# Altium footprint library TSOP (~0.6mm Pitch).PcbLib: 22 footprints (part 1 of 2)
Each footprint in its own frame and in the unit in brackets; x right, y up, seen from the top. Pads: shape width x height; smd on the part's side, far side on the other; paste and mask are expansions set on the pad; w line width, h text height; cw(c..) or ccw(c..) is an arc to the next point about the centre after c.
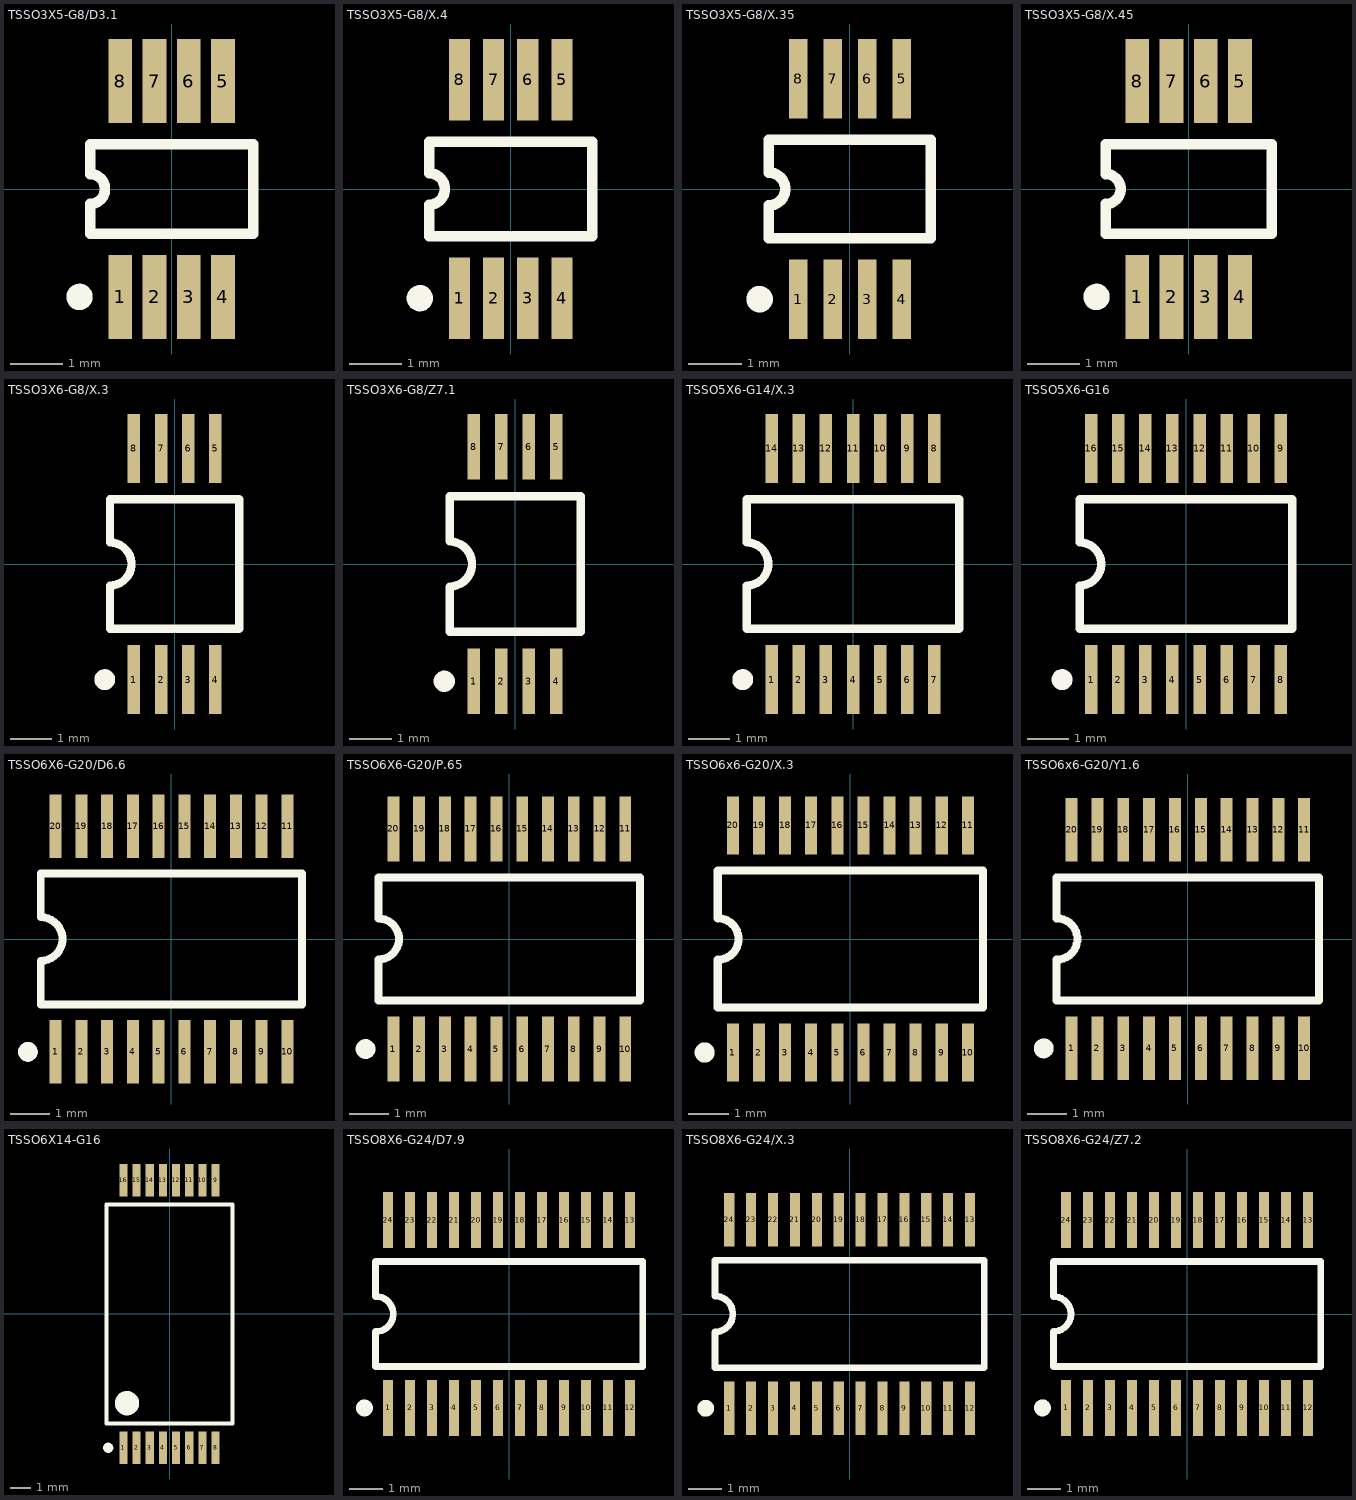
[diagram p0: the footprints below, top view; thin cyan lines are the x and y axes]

## TSSO3X5-G8/D3.1 [mm]
pads (8):
  rect 0.45x1.6 smd: 1(-0.975,-2.05) 2(-0.325,-2.05) 3(0.325,-2.05) 4(0.975,-2.05) 5(0.975,2.05) 6(0.325,2.05) 7(-0.325,2.05) 8(-0.975,2.05)
Top Overlay:
  circle w0.25: c-1.75,-2.05 r0.125
  lines w0.2: -1.55,-0.85 1.55,-0.85 1.55,0.85 -1.55,0.85 -1.55,0.283 cw(c-1.55,0) -1.55,-0.283 -1.55,-0.85

## TSSO3X5-G8/X.4 [mm]
pads (8):
  rect 0.4x1.55 smd: 1(-0.975,-2.075) 2(-0.325,-2.075) 3(0.325,-2.075) 4(0.975,-2.075) 5(0.975,2.075) 6(0.325,2.075) 7(-0.325,2.075) 8(-0.975,2.075)
Top Overlay:
  circle w0.25: c-1.725,-2.075 r0.125
  lines w0.2: -1.55,-0.9 1.55,-0.9 1.55,0.9 -1.55,0.9 -1.55,0.3 cw(c-1.55,0) -1.55,-0.3 -1.55,-0.9

## TSSO3X5-G8/X.35 [mm]
pads (8):
  rect 0.35x1.5 smd: 1(-0.975,-2.075) 2(-0.325,-2.075) 3(0.325,-2.075) 4(0.975,-2.075) 5(0.975,2.075) 6(0.325,2.075) 7(-0.325,2.075) 8(-0.975,2.075)
Top Overlay:
  circle w0.25: c-1.7,-2.075 r0.125
  lines w0.2: -1.525,-0.925 -1.525,-0.308 ccw(c-1.525,0) -1.525,0.308 -1.525,0.925 1.525,0.925 1.525,-0.925 -1.525,-0.925

## TSSO3X5-G8/X.45 [mm]
pads (8):
  rect 0.45x1.6 smd: 1(-0.975,-2.05) 2(-0.325,-2.05) 3(0.325,-2.05) 4(0.975,-2.05) 5(0.975,2.05) 6(0.325,2.05) 7(-0.325,2.05) 8(-0.975,2.05)
Top Overlay:
  circle w0.25: c-1.75,-2.05 r0.125
  lines w0.2: -1.575,-0.85 -1.575,-0.283 ccw(c-1.575,0) -1.575,0.283 -1.575,0.85 1.575,0.85 1.575,-0.85 -1.575,-0.85

## TSSO3X6-G8/X.3 [mm]
pads (8):
  rect 0.3x1.65 smd: 1(-0.975,-2.775) 2(-0.325,-2.775) 3(0.325,-2.775) 4(0.975,-2.775) 5(0.975,2.775) 6(0.325,2.775) 7(-0.325,2.775) 8(-0.975,2.775)
Top Overlay:
  circle w0.25: c-1.675,-2.775 r0.125
  lines w0.2: -1.55,-1.55 1.55,-1.55 1.55,1.55 -1.55,1.55 -1.55,0.517 cw(c-1.55,0) -1.55,-0.517 -1.55,-1.55

## TSSO3X6-G8/Z7.1 [mm]
pads (8):
  rect 0.3x1.55 smd: 1(-0.975,-2.775) 2(-0.325,-2.775) 3(0.325,-2.775) 4(0.975,-2.775) 5(0.975,2.775) 6(0.325,2.775) 7(-0.325,2.775) 8(-0.975,2.775)
Top Overlay:
  circle w0.25: c-1.675,-2.775 r0.125
  lines w0.2: -1.55,-1.6 1.55,-1.6 1.55,1.6 -1.55,1.6 -1.55,0.533 cw(c-1.55,0) -1.55,-0.533 -1.55,-1.6

## TSSO5X6-G14/X.3 [mm]
pads (14):
  rect 0.3x1.65 smd: 1(-1.95,-2.775) 2(-1.3,-2.775) 3(-0.65,-2.775) 4(0,-2.775) 5(0.65,-2.775) 6(1.3,-2.775) 7(1.95,-2.775) 8(1.95,2.775) 9(1.3,2.775) 10(0.65,2.775) 11(0,2.775) 12(-0.65,2.775) 13(-1.3,2.775) 14(-1.95,2.775)
Top Overlay:
  circle w0.25: c-2.65,-2.775 r0.125
  lines w0.2: -2.55,-1.55 2.55,-1.55 2.55,1.55 -2.55,1.55 -2.55,0.517 cw(c-2.55,0) -2.55,-0.517 -2.55,-1.55

## TSSO5X6-G16 [mm]
pads (16):
  rect 0.3x1.65 smd: 1(-2.275,-2.775) 2(-1.625,-2.775) 3(-0.975,-2.775) 4(-0.325,-2.775) 5(0.325,-2.775) 6(0.975,-2.775) 7(1.625,-2.775) 8(2.275,-2.775) 9(2.275,2.775) 10(1.625,2.775) 11(0.975,2.775) 12(0.325,2.775) 13(-0.325,2.775) 14(-0.975,2.775) 15(-1.625,2.775) 16(-2.275,2.775)
Top Overlay:
  circle w0.25: c-2.975,-2.775 r0.125
  lines w0.2: -2.55,-1.55 -2.55,-0.517 ccw(c-2.55,0) -2.55,0.517 -2.55,1.55 2.55,1.55 2.55,-1.55 -2.55,-1.55

## TSSO6X6-G20/D6.6 [mm]
pads (20):
  rect 0.3x1.6 smd: 1(-2.925,-2.85) 2(-2.275,-2.85) 3(-1.625,-2.85) 4(-0.975,-2.85) 5(-0.325,-2.85) 6(0.325,-2.85) 7(0.975,-2.85) 8(1.625,-2.85) 9(2.275,-2.85) 10(2.925,-2.85) 11(2.925,2.85) 12(2.275,2.85) 13(1.625,2.85) 14(0.975,2.85) 15(0.325,2.85) 16(-0.325,2.85) 17(-0.975,2.85) 18(-1.625,2.85) 19(-2.275,2.85) 20(-2.925,2.85)
Top Overlay:
  circle w0.25: c-3.625,-2.85 r0.125
  lines w0.2: -3.3,-1.65 -3.3,-0.55 ccw(c-3.3,0) -3.3,0.55 -3.3,1.65 3.3,1.65 3.3,-1.65 -3.3,-1.65

## TSSO6X6-G20/P.65 [mm]
pads (20):
  rect 0.3x1.65 smd: 1(-2.925,-2.775) 2(-2.275,-2.775) 3(-1.625,-2.775) 4(-0.975,-2.775) 5(-0.325,-2.775) 6(0.325,-2.775) 7(0.975,-2.775) 8(1.625,-2.775) 9(2.275,-2.775) 10(2.925,-2.775) 11(2.925,2.775) 12(2.275,2.775) 13(1.625,2.775) 14(0.975,2.775) 15(0.325,2.775) 16(-0.325,2.775) 17(-0.975,2.775) 18(-1.625,2.775) 19(-2.275,2.775) 20(-2.925,2.775)
Top Overlay:
  circle w0.25: c-3.625,-2.775 r0.125
  lines w0.2: -3.3,-1.55 -3.3,-0.517 ccw(c-3.3,0) -3.3,0.517 -3.3,1.55 3.3,1.55 3.3,-1.55 -3.3,-1.55

## TSSO6x6-G20/X.3 [mm]
pads (20):
  rect 0.3x1.45 smd: 1(-2.925,-2.825) 2(-2.275,-2.825) 3(-1.625,-2.825) 4(-0.975,-2.825) 5(-0.325,-2.825) 6(0.325,-2.825) 7(0.975,-2.825) 8(1.625,-2.825) 9(2.275,-2.825) 10(2.925,-2.825) 11(2.925,2.825) 12(2.275,2.825) 13(1.625,2.825) 14(0.975,2.825) 15(0.325,2.825) 16(-0.325,2.825) 17(-0.975,2.825) 18(-1.625,2.825) 19(-2.275,2.825) 20(-2.925,2.825)
Top Overlay:
  circle w0.25: c-3.625,-2.825 r0.125
  lines w0.2: -3.3,-0.52 -3.3,-1.7 3.3,-1.7 3.3,1.7 -3.3,1.7 -3.3,0.52 ; -3.3,-0.517 ccw(c-3.3,0) -3.3,0.517

## TSSO6x6-G20/Y1.6 [mm]
pads (20):
  rect 0.3x1.6 smd: 1(-2.925,-2.75) 2(-2.275,-2.75) 3(-1.625,-2.75) 4(-0.975,-2.75) 5(-0.325,-2.75) 6(0.325,-2.75) 7(0.975,-2.75) 8(1.625,-2.75) 9(2.275,-2.75) 10(2.925,-2.75) 11(2.925,2.75) 12(2.275,2.75) 13(1.625,2.75) 14(0.975,2.75) 15(0.325,2.75) 16(-0.325,2.75) 17(-0.975,2.75) 18(-1.625,2.75) 19(-2.275,2.75) 20(-2.925,2.75)
Top Overlay:
  circle w0.25: c-3.625,-2.75 r0.125
  lines w0.2: -3.3,-1.55 3.3,-1.55 3.3,1.55 -3.3,1.55 -3.3,0.52 cw(c-3.3,0) -3.3,-0.52 -3.3,-1.55

## TSSO6X14-G16 [mm]
pads (16):
  rect 0.4x1.6 smd: 1(-2.275,-6.6) 2(-1.625,-6.6) 3(-0.975,-6.6) 4(-0.325,-6.6) 5(0.325,-6.6) 6(0.975,-6.6) 7(1.625,-6.6) 8(2.275,-6.6) 9(2.275,6.6) 10(1.625,6.6) 11(0.975,6.6) 12(0.325,6.6) 13(-0.325,6.6) 14(-0.975,6.6) 15(-1.625,6.6) 16(-2.275,6.6)
Top Overlay:
  circle w0.6: c-2.1,-4.4 r0.3
  circle w0.25: c-3.025,-6.6 r0.125
  lines w0.2: -3.1,-5.4 3.1,-5.4 3.1,5.4 -3.1,5.4 -3.1,-0.635 -3.1,-5.4

## TSSO8X6-G24/D7.9 [mm]
pads (24):
  rect 0.3x1.65 smd: 1(-3.575,-2.775) 2(-2.925,-2.775) 3(-2.275,-2.775) 4(-1.625,-2.775) 5(-0.975,-2.775) 6(-0.325,-2.775) 7(0.325,-2.775) 8(0.975,-2.775) 9(1.625,-2.775) 10(2.275,-2.775) 11(2.925,-2.775) 12(3.575,-2.775) 13(3.575,2.775) 14(2.925,2.775) 15(2.275,2.775) 16(1.625,2.775) 17(0.975,2.775) 18(0.325,2.775) 19(-0.325,2.775) 20(-0.975,2.775) 21(-1.625,2.775) 22(-2.275,2.775) 23(-2.925,2.775) 24(-3.575,2.775)
Top Overlay:
  circle w0.25: c-4.275,-2.775 r0.125
  lines w0.2: -3.95,-0.52 -3.95,-1.55 3.95,-1.55 3.95,1.55 -3.95,1.55 -3.95,0.52 ; -3.943,-0.52 ccw(c-3.943,0) -3.943,0.52

## TSSO8X6-G24/X.3 [mm]
pads (24):
  rect 0.3x1.6 smd: 1(-3.575,-2.8) 2(-2.925,-2.8) 3(-2.275,-2.8) 4(-1.625,-2.8) 5(-0.975,-2.8) 6(-0.325,-2.8) 7(0.325,-2.8) 8(0.975,-2.8) 9(1.625,-2.8) 10(2.275,-2.8) 11(2.925,-2.8) 12(3.575,-2.8) 13(3.575,2.8) 14(2.925,2.8) 15(2.275,2.8) 16(1.625,2.8) 17(0.975,2.8) 18(0.325,2.8) 19(-0.325,2.8) 20(-0.975,2.8) 21(-1.625,2.8) 22(-2.275,2.8) 23(-2.925,2.8) 24(-3.575,2.8)
Top Overlay:
  circle w0.25: c-4.275,-2.8 r0.125
  lines w0.2: -4,-1.6 -4,-0.533 ccw(c-4,0) -4,0.533 -4,1.6 4,1.6 4,-1.6 -4,-1.6

## TSSO8X6-G24/Z7.2 [mm]
pads (24):
  rect 0.3x1.65 smd: 1(-3.575,-2.775) 2(-2.925,-2.775) 3(-2.275,-2.775) 4(-1.625,-2.775) 5(-0.975,-2.775) 6(-0.325,-2.775) 7(0.325,-2.775) 8(0.975,-2.775) 9(1.625,-2.775) 10(2.275,-2.775) 11(2.925,-2.775) 12(3.575,-2.775) 13(3.575,2.775) 14(2.925,2.775) 15(2.275,2.775) 16(1.625,2.775) 17(0.975,2.775) 18(0.325,2.775) 19(-0.325,2.775) 20(-0.975,2.775) 21(-1.625,2.775) 22(-2.275,2.775) 23(-2.925,2.775) 24(-3.575,2.775)
Top Overlay:
  circle w0.25: c-4.275,-2.775 r0.125
  lines w0.2: -3.95,-1.55 -3.95,-0.517 ccw(c-3.95,0) -3.95,0.517 -3.95,1.55 3.95,1.55 3.95,-1.55 -3.95,-1.55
